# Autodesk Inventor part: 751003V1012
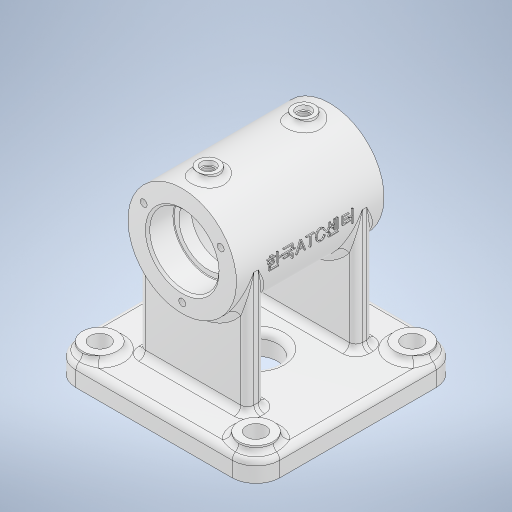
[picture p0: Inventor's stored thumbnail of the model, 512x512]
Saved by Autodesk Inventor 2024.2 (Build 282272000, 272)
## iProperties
Created: 2025-10
Part Number: 751003V1012
Material: 알루미늄 6061
Document SubType Name: Modeling
Designer: home
Mass: 503.821 g
Surface Area: 499.354 cm^2
Volume: 186.6 cm^3
Density: 2.7 g/cm^3
Appearance: 알루미늄 - 평지
Author: home
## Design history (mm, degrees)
sketch "스케치1"
  geometry: L1 (0, 34)-(0, -34); L2 (25, -34)-(25, 0); L3 (25, -34)-(17, -34); L4 (16, -33)-(16, -22.3); L5 (15.7, -22)-(13.5, -22); L6 (13.5, -22)-(13.5, -16.258); L7 (13.5, -16.258)-(19.598, -5.696); L8 (20, -4.196)-(20, 0); L9 (17, -34)-(16, -33); L10 (0, 0)-(-6.884, 0); L11 (20, 4.196)-(20, 0); L12 (13.5, 16.258)-(19.598, 5.696); L13 (15.7, 22)-(13.5, 22); L14 (25, 34)-(25, 0); L15 (16, 33)-(16, 22.3); L16 (25, 34)-(17, 34); L17 (17, 34)-(16, 33); L18 (13.5, 22)-(13.5, 16.258); A1 r 0.3 centre (15.7, -22.3) between (16, -22.3) and (15.7, -22); A2 r 3 centre (17, -4.196) between (19.598, -5.696) and (20, -4.196); A3 r 3 centre (17, 4.196) between (20, 4.196) and (19.598, 5.696); A4 r 0.3 centre (15.7, 22.3) between (15.7, 22) and (16, 22.3); 9 further points
  constraints: 36 end point, 15 symmetric about line, 12 point on line, 8 point on circle, 4 centre point, 4 tangent, 3 horizontal alignment, 3 perpendicular, 2 horizontal, 2 midpoint, 2 vertical, 1 coincident, 1 parallel, 2 other
  dimensions: "d0" = 68 distance of L1.start L1.end; "d1" = 50 diameter of L2 L1; "d2" = 12 distance of point (16, -34) point (16, -22); "d3" = 32 diameter of L4 L1; "d4" = 27 diameter of point (13.5, -19.129) L1; "d5" = 30 deg angle of L1 L7; "d6" = 5 distance of point (20, -5) L8.end; "d7" = 40 diameter of L8 L1; "d8" = 1 distance of L3.end point (16, -34); "d9" = 1 distance of L4.start point (16, -34) (= d8); "d10" = 0.3 radius of A1 (derived); "d11" = 3 radius of A2
revolve "회전1" sketch "스케치1" stored, may be unused: angle "d12" = 90 deg
node "작업 평면1"
sketch "스케치2"
  geometry: L1 (36, -47)-(-36, -47); L2 (-47, -36)-(-47, 36); L3 (-36, 47)-(36, 47); L4 (47, 36)-(47, -36); L5 (47, -47)-(-47, 47); L6 (-47, -47)-(47, 47); C1 r 8 at (36, -36); C2 r 8 at (36, 36); C3 r 8 at (-36, -36); C4 r 8 at (-36, 36); A1 r 11 centre (36, 36) between (47, 36) and (36, 47); A2 r 11 centre (-36, 36) between (-36, 47) and (-47, 36); A3 r 11 centre (-36, -36) between (-47, -36) and (-36, -47); A4 r 11 centre (36, -36) between (36, -47) and (47, -36); 1 further point
  constraints: 12 end point, 9 point on line, 8 centre point, 8 point on circle, 8 tangent, 6 equal radius, 4 coincident, 2 midpoint, 2 parallel, 1 horizontal, 1 perpendicular
  dimensions: "d14" = 94 distance of L5.end L6.end; "d15" = 94 distance of L6.start L5.end; "d16" = 11 radius of A1; "d17" = 16 diameter of C1
extrude "돌출1" join sketch "스케치2" distance "d19" = 10; taper "d20" = 0 deg
extrude "돌출2" join sketch "스케치2" distance "d21" = 13; taper "d22" = 0 deg
sketch "스케치3"
  geometry: C1 r 8 at (0, 0) reference; C2 r 8 at (72, 0) reference; C3 r 8 at (72, 72) reference; C4 r 8 at (0, 72) reference; 5 further points
  constraints: 4 coincident
hole "구멍1" sketch "스케치3" at (0, 0), (72, 0), (72, 72), (0, 72) diameter "d23" = 9; stored, may be unused: countersink angle "d27" = 90 deg, drill point angle "d29" = 0 deg; dims "d24" = 8, "d25" = 4, "d26" = 2, "d28" = 13
sketch "스케치4"
  geometry: L1 (-25, 29)-(25, 29); L2 (0, 0)-(-7.129, 0); L3 (-25, 29)-(-25, 21); L4 (-25, 21)-(25, 21); L5 (25, 21)-(25, 29); L6 (-25, -29)-(25, -29); L7 (25, -21)-(25, -29); L8 (-25, -21)-(25, -21); L9 (-25, -29)-(-25, -21); 4 further points
  constraints: 18 end point, 6 symmetric about line, 2 horizontal, 2 midpoint, 2 perpendicular, 1 vertical, 1 vertical alignment
  dimensions: "d30" = 8 distance of L1.start L3.end; "d31" = 21 distance between parallel lines of L2 L4; "d32" = 50 distance from line of point (25, 25) L3
extrude "돌출3" join sketch "스케치4" stored distance "d33" = 13; taper "d34" = 0 deg
fillet "모깎기1" dims "d35" = 3
sketch "스케치5"
  geometry: C1 r 10 at (0, 0); 1 further point
  constraints: 1 centre point, 1 coincident
  dimensions: "d36" = 20 diameter of C1
extrude "돌출4" cut sketch "스케치5" extent not by distance; stored distance "d37" = 0; taper "d38" = 0 deg
fillet "모깎기2" dims "d39" = 3
sketch "스케치6" dims "d47" = 41
  geometry: L1 (0, 0)-(17.754, 10.25); L2 (0, 0)-(0, 10.459); C1 r 25 at (0, 0) reference; 3 further points
  constraints: 4 end point, 1 coincident, 1 vertical, 7 other
  dimensions: "d48" = 60 deg angle of L2 L1; "d51" = 360 deg dimension on L1.start L1.end (derived)
hole "구멍2" sketch "스케치6" at (17.754, 10.25), (-17.754, 10.25), (0, -20.5) diameter "d40" = 3.242; stored, may be unused: countersink angle "d44" = 90 deg, drill point angle "d46" = 118 deg; dims "d41" = 8, "d42" = 4, "d43" = 2, "d45" = 10
node "작업 평면2"
sketch "스케치7"
  geometry: L1 (-25, -34)-(25, -34) reference; C1 r 5 at (0, -22); C2 r 3.3 at (0, -22); 1 further point
  constraints: 2 centre point, 1 coincident, 1 vertical alignment
  dimensions: "d54" = 10 diameter of C1; "d55" = 12 distance from line of L1 C1.centre; "d56" = 6.6 diameter of C2
extrude "돌출5" join sketch "스케치7" stored distance "d57" = 10; taper "d58" = 0 deg
extrude "돌출6" cut sketch "스케치7" distance "d59" = 2; taper "d60" = 0 deg
sketch "스케치8"
  geometry: C1 r 3.3 at (0, 0) reference; 2 further points
  constraints: 1 coincident
hole "구멍3" sketch "스케치8" at (0, 0) diameter "d61" = 5.1881; stored, may be unused: countersink angle "d65" = 90 deg, drill point angle "d67" = 118 deg; dims "d62" = 12, "d63" = 4, "d64" = 2, "d66" = 16
fillet "모깎기3" dims "d68" = 3
node "작업 평면4"
  node "작업 평면3"
sketch "스케치9"
  geometry: C1 r 6 at (0, 0); 1 further point
  constraints: 1 centre point, 1 coincident
  dimensions: "d70" = 12 diameter of C1
extrude "돌출7" join sketch "스케치9" stored distance "d71" = 2; taper "d72" = 0 deg
sketch "스케치10"
  geometry: C1 r 6 at (0, 0) reference; 2 further points
  constraints: 1 coincident
hole "구멍4" sketch "스케치10" at (0, 0) diameter "d73" = 5.1881; stored, may be unused: countersink angle "d77" = 90 deg, drill point angle "d79" = 118 deg; dims "d74" = 12, "d75" = 4, "d76" = 2, "d78" = 16
fillet "모깎기4" dims "d80" = 3
sketch "스케치11"
  geometry: L1 (83, 0)-(72, 0) reference; 2 further points
  constraints: 1 coincident, 1 other
  dimensions: "d81" = 66 distance from line of L1 point (36, 66)
feature "엠보싱1" sketch "스케치11" dims "d82" = 0.5, "d83" = 0
node "솔리드1"
mirror "미러1"
mirror "미러2"
feature "A9D066F2-1C7D-4E18-AEED-F7BC21143FA4" dims "d23" = 9, "d24" = 8, "d25" = 4, "d26" = 2, "d27" = 90 deg, "d28" = 13, "d29" = 0
other parameters: "d13" = -66, "d53" = -94, "d69" = 3
